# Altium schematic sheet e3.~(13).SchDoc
size custom portrait; Address1: Address1; Address2: Address2; Address3: Address3; Address4: Address4; SheetNumber: 1; SheetTotal: 1; Scale: 1:1; Разраб.: Иванов; Обозначение документа: АБВГ.123456.001Э3; Пров.: Петров; Утв.: Сидоров; Наименование организации: ОАО "Ваша фирма"; Перв. применение: АБВГ.123456.000; Наименование изделия 1: Плата; Наименование изделия 2: Схема электрическая; Наименование изделия 3: принципиальная; Нач. отд.: Нач. отд.; Фамилия нач. отд.: Сидоров
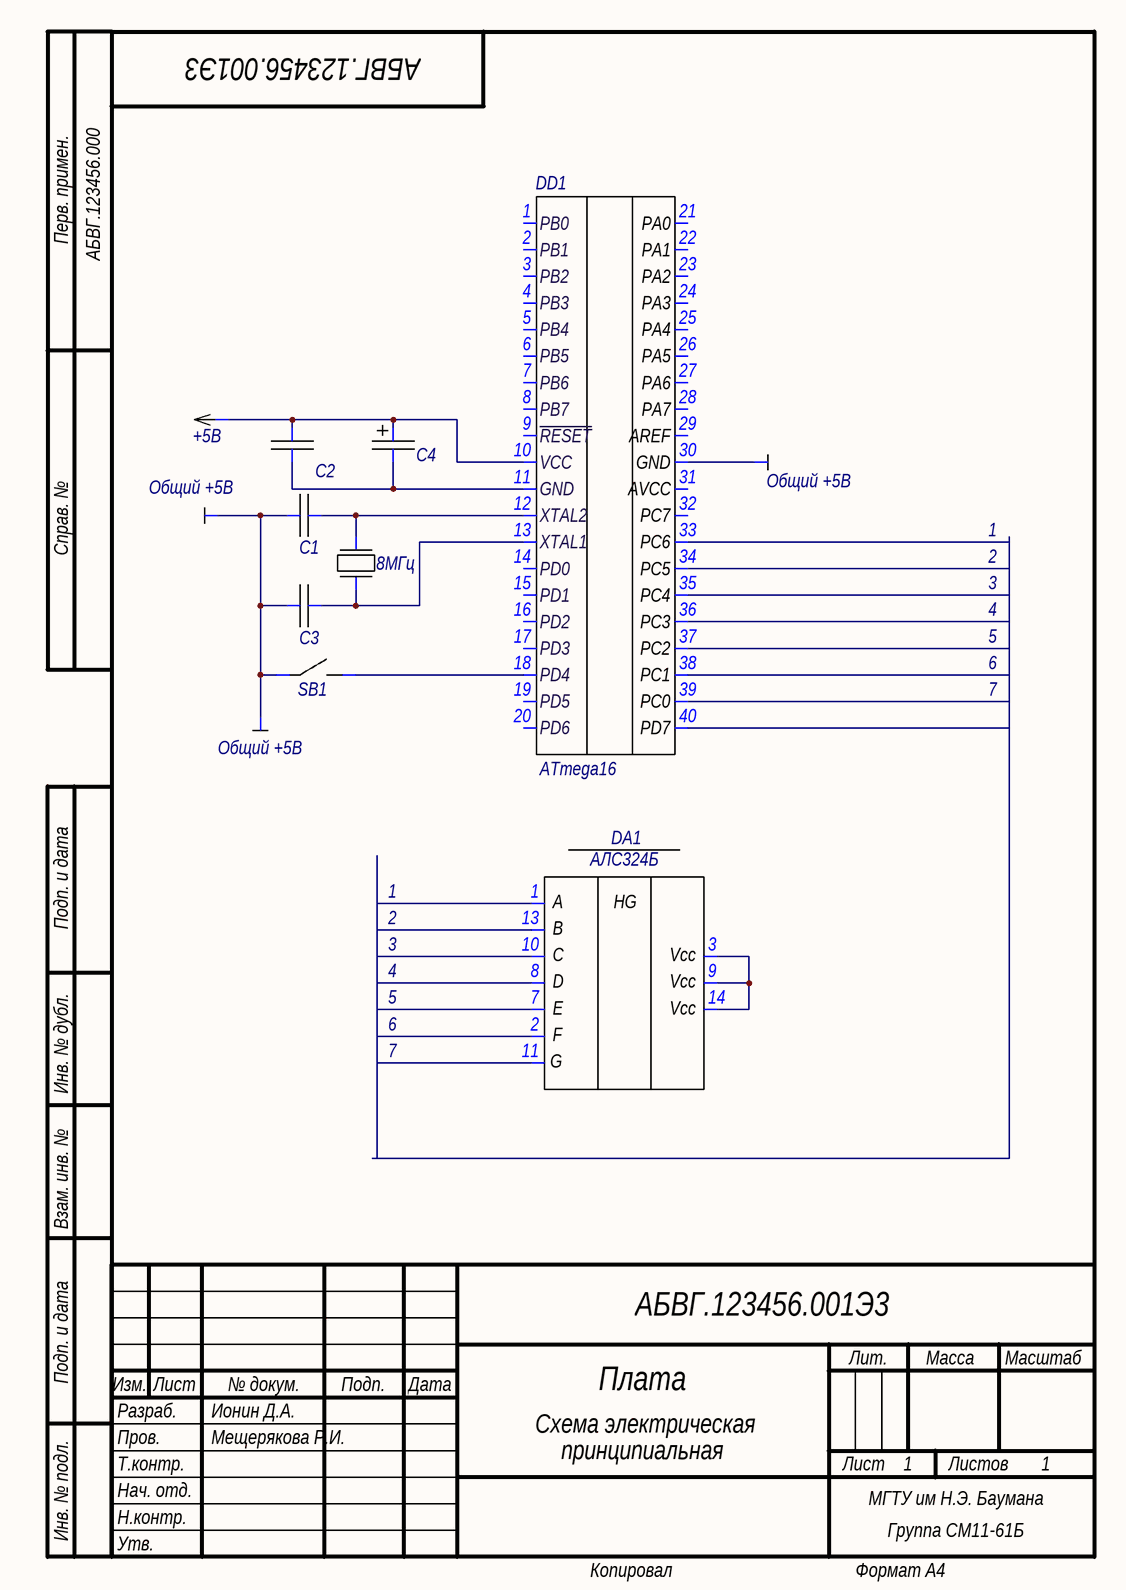
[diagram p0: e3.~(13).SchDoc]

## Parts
(Parts that share a designator on the sheet are numbered #1, #2 ... from top to bottom, then left to right.)
8МГц  8МГц
+5В  +5В
C1  Capacitor  (value not drawn)
C2  Capacitor  (value not drawn)
C3  Capacitor  (value not drawn)
C4  Capacitor +  (value not drawn)
DA1  АЛС324Б
DD1  ATmega16
SB1  Ключ  (value not drawn)
Общий_+5В  Общий +5В
Общий_+?#1  Общий +5В
Общий_+?#2  Общий +5В

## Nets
Net8МГц_1: 8МГц.1 C3.2 DD1.13(XTAL1)
Net8МГц_2: 8МГц.2 C1.2 DD1.12(XTAL2)
Net+5В_1: +5В.1 C2.2 C4.2 DD1.10(VCC)
NetC1_1: C1.1 C3.1 SB1.1 Общий_+5В.1 Общий_+?#2.1
NetC2_1: C2.1 C4.1 DD1.11(GND)
NetDA1_3: DA1.3 DA1.9 DA1.14
NetDD1_18: DD1.18(PD4) SB1.2
NetDD1_30: DD1.30(GND) Общий_+?#1.1

Not connected (* = marked no-connect by the designer): DA1 1 2 7 8 10 11 13; DD1 1(PB0) 2(PB1) 3(PB2) 4(PB3) 5(PB4) 6(PB5) 7(PB6) 8(PB7) 9(~{RESET}) 14(PD0) 15(PD1) 16(PD2) 17(PD3) 19(PD5) 20(PD6) 21(PA0) 22(PA1) 23(PA2) 24(PA3) 25(PA4) 26(PA5) 27(PA6) 28(PA7) 29(AREF) 31(AVCC) 32(PC7) 33(PC6) 34(PC5) 35(PC4) 36(PC3) 37(PC2) 38(PC1) 39(PC0) 40(PD7)

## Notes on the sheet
- Перв. примен.
- Справ. №
- 1
- 2
- 3
- 4
- 5
- 6
- 7
- Подп. и дата
- Инв. № дубл.
- Взам. инв. №
- Разраб.
- Изм.
- Лист
- Ионин Д.А.
- № докум.
- Подп.
- Дата
- Лит.
- Масса
- Масштаб
- Пров.
- Т.контр.
- Мещерякова Р.И.
- Листов
- Инв. № подл.
- Утв.
- Н.контр.
- МГТУ им Н.Э. Баумана
- Группа СМ11-61Б
- Копировал
- Формат А4

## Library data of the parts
8МГц = кварцевый резонатор
+5В = питание
Общий_+5В Общий_+?#1 Общий_+?#2 = земля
